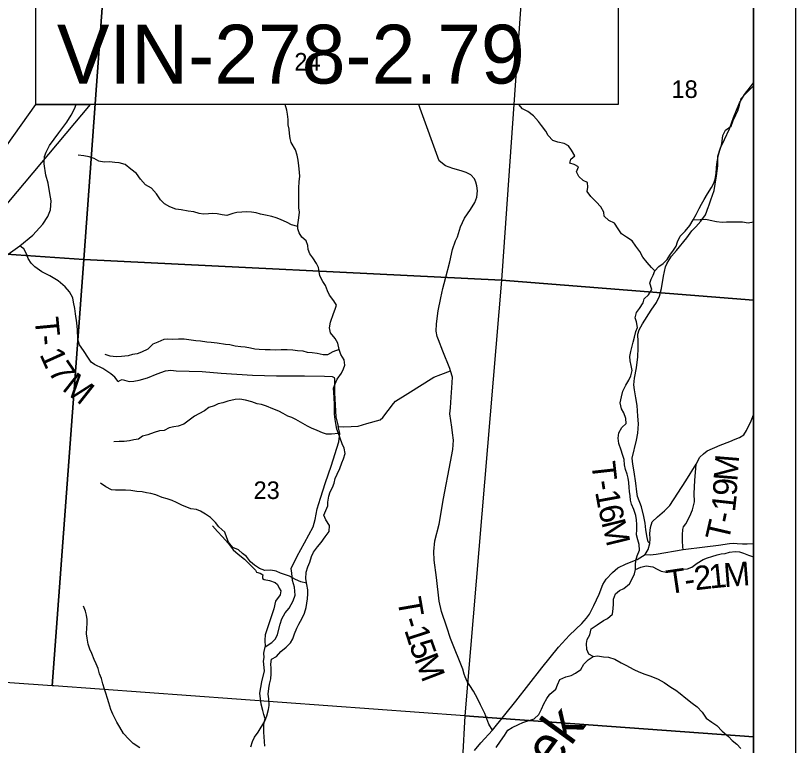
# Model space of a CAD drawing. Extents: x 0 to 34, y 0 to 22.
# Drawn here: x 7.144 to 9, y 16.66 to 18.398 of the extents above; entities that cross this region are included whole.
import ezdxf

# ---------------------------------------------------------------- set-up
doc = ezdxf.new("R2010")
doc.units = 0
for name, color, linetype in [('Default', 7, 'Continuous'), ('GM_X_County_Road', 7, 'Continuous'), ('GM_X_Minor_River', 7, 'Continuous'), ('GM_X_Minor_River_Text', 7, 'Continuous'), ('GM_X_Section', 7, 'Continuous'), ('GM_X_Section_Text', 7, 'Continuous'), ('GM_X_Township_Road', 7, 'Continuous'), ('GM_X_Township_Road_Text', 7, 'Continuous'), ('SC_Scratch1', 7, 'Continuous'), ('SH_Data', 7, 'Continuous'), ('SH_Text', 7, 'Continuous')]:
    doc.layers.add(name, color=color, linetype=linetype)

msp = doc.modelspace()

# ---------------------------------------------------------------- linework, layer by layer
at = {"layer": 'Default'}
for points in [[(8.9, 17.7203), (8.9, 18.739), (8.3709, 18.7757), (8.3007, 17.7677)], [(8.9, 16.6804), (8.9, 17.7203), (8.3007, 17.7677), (8.213, 16.7303)], [(8.9, 15.6488), (8.9, 16.6804), (8.213, 16.7303), (8.1912, 16.3241), (8.1695, 15.9195), (8.158, 15.705), (8.5934, 15.672)]]:
    msp.add_lwpolyline(points, close=True, dxfattribs=at)
at = {"layer": 'GM_X_County_Road'}
msp.add_lwpolyline([(8.2361, 16.6479), (8.2514, 16.6664), (8.2787, 16.6962), (8.3347, 16.7653), (8.396, 16.8445), (8.4361, 16.8936), (8.4623, 16.9227), (8.4917, 16.9506), (8.5026, 16.9628), (8.5098, 16.9725), (8.5203, 16.9928), (8.5325, 17.02), (8.5415, 17.0431), (8.5496, 17.0555), (8.5644, 17.072), (8.5773, 17.0825), (8.5971, 17.0927), (8.6231, 17.1023), (8.6426, 17.1142), (8.6498, 17.1266), (8.6531, 17.1404), (8.6541, 17.1519), (8.6537, 17.1648), (8.6548, 17.1791), (8.6591, 17.1924), (8.672, 17.2044), (8.6882, 17.2184), (8.7008, 17.2313), (8.7388, 17.2898), (8.7638, 17.3294), (8.7726, 17.346), (8.781, 17.3539), (8.79, 17.3611), (8.821, 17.3751), (8.8437, 17.384), (8.8563, 17.3892), (8.8668, 17.3933), (8.8771, 17.3997), (8.8835, 17.4097), (8.8943, 17.4326), (8.9, 17.4468)], dxfattribs=at)
at = {"layer": 'GM_X_Minor_River'}
for points in [[(8.8089, 18.0085), (8.8112, 18.0218), (8.8119, 18.0358), (8.8134, 18.0498), (8.8168, 18.0662), (8.8198, 18.0775), (8.824, 18.0893), (8.8259, 18.0992), (8.8274, 18.1121), (8.8338, 18.125), (8.8467, 18.1345), (8.8516, 18.1477), (8.8584, 18.1614), (8.8633, 18.1709), (8.8667, 18.1845), (8.8708, 18.2008), (8.8822, 18.2126), (8.8912, 18.2221), (8.9, 18.2307)], [(7.9044, 17.2957), (7.9093, 17.3056), (7.9153, 17.3192), (7.9199, 17.3325), (7.924, 17.342), (7.9285, 17.3553), (7.9259, 17.3674), (7.9209, 17.3784), (7.916, 17.3917), (7.9122, 17.4023), (7.9084, 17.4133), (7.9061, 17.4262), (7.9046, 17.436), (7.9027, 17.4489), (7.9027, 17.4626), (7.903, 17.4728), (7.9019, 17.4873), (7.9015, 17.5005), (7.9007, 17.5104), (7.9045, 17.521), (7.9094, 17.532), (7.9196, 17.5461), (7.9241, 17.5563), (7.9275, 17.5658), (7.9256, 17.5783), (7.9181, 17.5908), (7.9139, 17.603), (7.9108, 17.6174), (7.9048, 17.6291), (7.893, 17.6424), (7.8911, 17.6542), (7.8934, 17.6678), (7.9001, 17.6883), (7.9043, 17.6985), (7.9077, 17.7084), (7.9012, 17.7186), (7.891, 17.7323), (7.8864, 17.7422), (7.8811, 17.7551), (7.8751, 17.7649), (7.8679, 17.7778), (7.8663, 17.7881), (7.8644, 17.7979), (7.8602, 17.8078), (7.8511, 17.8207), (7.8439, 17.8305), (7.8405, 17.8411), (7.8394, 17.8506), (7.8356, 17.8612), (7.825, 17.8703), (7.8185, 17.8806), (7.8159, 17.8901), (7.8155, 17.8999), (7.8181, 17.9159), (7.8192, 17.9295), (7.8181, 17.9401), (7.8177, 17.9534), (7.8176, 17.9872), (7.8191, 18.0027), (7.8206, 18.0149), (7.8199, 18.0247), (7.8176, 18.0399), (7.8164, 18.0539), (7.8141, 18.0653), (7.8096, 18.0782), (7.7993, 18.0953), (7.7974, 18.1055), (7.7959, 18.1173), (7.7951, 18.1275), (7.7928, 18.1378), (7.7925, 18.1503), (7.7913, 18.1628), (7.789, 18.1723), (7.7855, 18.186)], [(8.6657, 17.7899), (8.6573, 17.7983), (8.6471, 17.81), (8.6369, 17.8229), (8.63, 17.8362), (8.6205, 17.8487), (8.6118, 17.8616), (8.5982, 17.8699), (8.5857, 17.8783), (8.5777, 17.8904), (8.5694, 17.9037), (8.5561, 17.9098), (8.5447, 17.9204), (8.5436, 17.9299), (8.5371, 17.9427), (8.5254, 17.9541), (8.5132, 17.967), (8.5041, 17.9792), (8.506, 17.9894), (8.5053, 18.0004), (8.495, 18.0049), (8.4848, 18.0148), (8.4791, 18.0254), (8.4836, 18.0376), (8.4734, 18.0432), (8.4632, 18.0463), (8.4651, 18.0558), (8.4749, 18.0641), (8.4673, 18.077), (8.4597, 18.0876), (8.4495, 18.0933), (8.4343, 18.0963), (8.4226, 18.1005), (8.4112, 18.1122), (8.4059, 18.1225), (8.3953, 18.1358), (8.3881, 18.1456), (8.3763, 18.1589), (8.3634, 18.1695), (8.3502, 18.1756), (8.3418, 18.186)], [(7.8156, 17.8956), (7.8007, 17.8999), (7.7905, 17.9052), (7.7746, 17.912), (7.7639, 17.9162), (7.7533, 17.9192), (7.7389, 17.9227), (7.7268, 17.9253), (7.7162, 17.928), (7.7049, 17.9298), (7.6927, 17.9302), (7.6825, 17.9298), (7.6704, 17.9287), (7.6606, 17.9268), (7.6466, 17.9219), (7.6352, 17.9234), (7.6235, 17.926), (7.6132, 17.9268), (7.603, 17.9256), (7.5913, 17.9249), (7.581, 17.9268), (7.5678, 17.9305), (7.5545, 17.932), (7.5379, 17.9351), (7.5254, 17.9366), (7.511, 17.9427), (7.4985, 17.9499), (7.489, 17.9593), (7.4791, 17.9734), (7.467, 17.987), (7.453, 17.9946), (7.4412, 18.0082), (7.4317, 18.0215), (7.4177, 18.0321), (7.4048, 18.0431), (7.3901, 18.0469), (7.3802, 18.0477), (7.367, 18.0496), (7.3545, 18.0492), (7.3416, 18.0514), (7.331, 18.0575), (7.3185, 18.0617), (7.3064, 18.0639), (7.2927, 18.0655)], [(8.5187, 16.8715), (8.5081, 16.8776), (8.5035, 16.8886), (8.5031, 16.9026), (8.5046, 16.9125), (8.5107, 16.9235), (8.514, 16.9375), (8.5284, 16.947), (8.5432, 16.9576), (8.553, 16.9622), (8.5648, 16.9724), (8.5659, 16.9861), (8.5666, 16.9963), (8.567, 17.0085), (8.5715, 17.021), (8.5813, 17.0286), (8.5916, 17.0335), (8.6048, 17.0445), (8.6124, 17.0582), (8.6173, 17.0684), (8.6192, 17.0787), (8.6191, 17.0897), (8.6199, 17.1003), (8.6237, 17.1117), (8.6289, 17.1246), (8.6278, 17.1382), (8.6251, 17.1496), (8.6221, 17.1617), (8.6225, 17.1743), (8.6228, 17.186), (8.622, 17.1974), (8.6198, 17.2076), (8.6152, 17.2217), (8.6099, 17.2342), (8.6072, 17.2437), (8.6065, 17.2543), (8.6053, 17.2642), (8.6045, 17.274), (8.6034, 17.2862), (8.6022, 17.296), (8.5992, 17.3055), (8.5958, 17.3173), (8.5931, 17.3279), (8.592, 17.3408), (8.5885, 17.3525), (8.5851, 17.3628), (8.5798, 17.3787), (8.5783, 17.3916), (8.5794, 17.4041), (8.587, 17.417), (8.5968, 17.4261), (8.5964, 17.4383), (8.5915, 17.4519), (8.5858, 17.4618), (8.5831, 17.4758), (8.5857, 17.4902), (8.5895, 17.5031), (8.5967, 17.5179), (8.6031, 17.5297), (8.6084, 17.5403), (8.6114, 17.5528), (8.6088, 17.565), (8.6065, 17.5756), (8.6061, 17.5858), (8.6083, 17.598), (8.6114, 17.6105), (8.614, 17.62), (8.6166, 17.6321), (8.6204, 17.6454), (8.6238, 17.6549), (8.6219, 17.6685), (8.6188, 17.6784), (8.6215, 17.6909), (8.6287, 17.7004), (8.6374, 17.7137), (8.64, 17.7232), (8.6506, 17.733), (8.6585, 17.7459), (8.6536, 17.7603), (8.6566, 17.7702), (8.6615, 17.7801), (8.6657, 17.7899), (8.6747, 17.8002), (8.685, 17.8074), (8.6948, 17.8169), (8.7012, 17.8271), (8.7099, 17.8389), (8.716, 17.8491), (8.7194, 17.8594), (8.7258, 17.8723), (8.7375, 17.8848), (8.7485, 17.8981), (8.7568, 17.9114), (8.7636, 17.9243), (8.7708, 17.9383), (8.7764, 17.9486), (8.7832, 17.9596), (8.7904, 17.9736), (8.7999, 17.9884), (8.8055, 17.999), (8.8089, 18.0085)], [(8.7568, 17.9114), (8.7734, 17.9121), (8.7871, 17.9133), (8.7973, 17.9106), (8.8121, 17.9072), (8.8253, 17.9061), (8.8363, 17.9065), (8.8738, 17.9065), (8.8878, 17.9046), (8.9, 17.9066)], [(7.9139, 17.603), (7.8991, 17.5969), (7.8862, 17.5897), (7.876, 17.5897), (7.8613, 17.5934), (7.8499, 17.595), (7.8385, 17.5953), (7.8283, 17.5984), (7.8147, 17.5999), (7.8037, 17.601), (7.7901, 17.6018), (7.7757, 17.6018), (7.7632, 17.601), (7.7495, 17.6017), (7.7378, 17.6021), (7.7238, 17.6029), (7.7132, 17.6036), (7.7026, 17.6059), (7.6901, 17.6082), (7.6802, 17.6089), (7.6662, 17.6108), (7.6537, 17.6138), (7.6431, 17.615), (7.6238, 17.6176), (7.609, 17.6191), (7.5992, 17.6203), (7.584, 17.6222), (7.5727, 17.6233), (7.5564, 17.6256), (7.5447, 17.6274), (7.5314, 17.6271), (7.5178, 17.6267), (7.5064, 17.6274), (7.4966, 17.6267), (7.4826, 17.6202), (7.4705, 17.6153), (7.4583, 17.6039), (7.4432, 17.5963), (7.433, 17.5925), (7.4216, 17.591), (7.4114, 17.5879), (7.3955, 17.5864), (7.383, 17.5856), (7.369, 17.5868), (7.3569, 17.5906)], [(7.912, 17.4029), (7.8959, 17.4011), (7.8838, 17.4008), (7.8743, 17.4042), (7.8618, 17.4099), (7.8482, 17.4155), (7.8384, 17.4205), (7.8277, 17.4265), (7.8111, 17.436), (7.8016, 17.4406), (7.7921, 17.4443), (7.7808, 17.4504), (7.7705, 17.4557), (7.7561, 17.4618), (7.741, 17.4675), (7.7289, 17.4716), (7.719, 17.4731), (7.7061, 17.4777), (7.691, 17.4818), (7.6777, 17.4841), (7.666, 17.4837), (7.6493, 17.4796), (7.6372, 17.4761), (7.6262, 17.4731), (7.6164, 17.4685), (7.6039, 17.4644), (7.5933, 17.4564), (7.5801, 17.4499), (7.5695, 17.4442), (7.557, 17.4344), (7.5438, 17.4253), (7.5305, 17.4199), (7.5207, 17.4188), (7.5089, 17.4158), (7.4976, 17.4101), (7.4866, 17.4089), (7.4737, 17.4047), (7.4586, 17.3998), (7.4457, 17.396), (7.4359, 17.3895), (7.4253, 17.3876), (7.4147, 17.3854), (7.4022, 17.3838), (7.3904, 17.3835), (7.3776, 17.3831)], [(7.8364, 17.0462), (7.8225, 17.0495), (7.8096, 17.0548), (7.7956, 17.0627), (7.7861, 17.0665), (7.774, 17.0699), (7.7642, 17.0745), (7.7509, 17.0771), (7.7373, 17.0767), (7.7244, 17.0813), (7.7126, 17.0889), (7.7032, 17.0972), (7.6937, 17.1101), (7.6842, 17.1173), (7.6744, 17.1253), (7.6611, 17.1309), (7.6501, 17.1442), (7.6467, 17.1545), (7.6414, 17.1674), (7.6273, 17.1806), (7.6198, 17.1905), (7.608, 17.2026), (7.5959, 17.2102), (7.5841, 17.2178), (7.5747, 17.2216), (7.561, 17.2231), (7.5512, 17.2276), (7.5413, 17.231), (7.5265, 17.2382), (7.5167, 17.2435), (7.5042, 17.2473), (7.4925, 17.2504), (7.4777, 17.2568), (7.4659, 17.2595), (7.455, 17.2617), (7.4447, 17.2636), (7.4319, 17.2647), (7.4178, 17.2666), (7.4057, 17.2674), (7.3951, 17.2674), (7.3815, 17.2681), (7.3716, 17.2685), (7.3584, 17.2753), (7.3455, 17.2841)], [(7.7033, 16.6568), (7.7074, 16.6689), (7.7127, 16.6792), (7.721, 16.6917), (7.7369, 16.7175), (7.7418, 16.7304), (7.7456, 16.7456), (7.7475, 16.7551), (7.7463, 16.771), (7.7452, 16.7816), (7.7467, 16.7957), (7.7478, 16.8055), (7.7512, 16.8184), (7.7523, 16.8306), (7.7523, 16.8442), (7.7515, 16.8537), (7.7527, 16.8651), (7.7651, 16.8719), (7.775, 16.8833), (7.7875, 16.8935), (7.798, 16.9042), (7.8037, 16.9137), (7.8079, 16.9254), (7.8132, 16.9391), (7.8177, 16.9486), (7.826, 16.9626), (7.8317, 16.9747), (7.8351, 16.988), (7.8373, 16.9983), (7.8384, 17.0093), (7.8392, 17.021), (7.8392, 17.0305), (7.8369, 17.0434), (7.8346, 17.0567), (7.8353, 17.0722), (7.8391, 17.0851), (7.844, 17.0961), (7.8482, 17.1094), (7.8531, 17.12), (7.8622, 17.1326), (7.8709, 17.1428), (7.8807, 17.1565), (7.8898, 17.1697), (7.8909, 17.1834), (7.8825, 17.1971), (7.8776, 17.2081), (7.8825, 17.2194), (7.887, 17.2301), (7.887, 17.2395), (7.8893, 17.2536), (7.8927, 17.2638), (7.8983, 17.2737), (7.9017, 17.2843), (7.9044, 17.2957)], [(8.6192, 17.0787), (8.632, 17.0847), (8.6449, 17.0878), (8.6604, 17.0848), (8.6707, 17.0795), (8.6801, 17.0749), (8.6934, 17.0726), (8.7063, 17.0761), (8.7176, 17.0787), (8.7324, 17.0795), (8.7434, 17.0806), (8.7532, 17.0844), (8.7664, 17.0939), (8.7801, 17.103), (8.791, 17.1064), (8.8013, 17.1099), (8.8134, 17.114), (8.8232, 17.1163), (8.8331, 17.1171), (8.8433, 17.1201), (8.8565, 17.122), (8.8667, 17.1209), (8.8762, 17.1175), (8.8887, 17.1129), (8.8982, 17.1099), (8.9, 17.1099)], [(7.4394, 16.6544), (7.4235, 16.6643), (7.4136, 16.6752), (7.4007, 16.6885), (7.3916, 16.7033), (7.3848, 16.7154), (7.3798, 16.7249), (7.3749, 16.7344), (7.3703, 16.7454), (7.3658, 16.7617), (7.3627, 16.772), (7.3582, 16.7841), (7.3555, 16.7936), (7.3517, 16.8065), (7.3483, 16.8194), (7.3434, 16.8307), (7.3399, 16.8429), (7.3354, 16.8543), (7.3308, 16.8645), (7.3248, 16.8789), (7.3202, 16.8895), (7.3168, 16.9013), (7.3141, 16.9157), (7.3122, 16.9256), (7.3133, 16.9396), (7.3137, 16.9495), (7.3137, 16.9601), (7.3122, 16.9699), (7.3103, 16.9798), (7.3053, 16.9919)], [(8.2876, 16.6548), (8.2978, 16.67), (8.3072, 16.6836), (8.3155, 16.6965), (8.3261, 16.7026), (8.3409, 16.7098), (8.3515, 16.7144), (8.378, 16.7235), (8.3893, 16.7337), (8.3958, 16.7459), (8.401, 16.7592), (8.4086, 16.7717), (8.4154, 16.7816), (8.4294, 16.7937), (8.4339, 16.8039), (8.4396, 16.8165), (8.4532, 16.8229), (8.4665, 16.8267), (8.4763, 16.8317), (8.4892, 16.8408), (8.4964, 16.8533), (8.5066, 16.8639), (8.5187, 16.8715), (8.5289, 16.873), (8.5429, 16.8711), (8.555, 16.87), (8.5698, 16.8651), (8.585, 16.8567), (8.5963, 16.8514), (8.6153, 16.8408), (8.627, 16.8351), (8.6418, 16.8295), (8.6531, 16.8257), (8.6634, 16.8219), (8.6732, 16.8173), (8.6872, 16.8098), (8.7035, 16.7988), (8.7157, 16.7912), (8.7259, 16.7836), (8.7395, 16.7722), (8.7543, 16.7605), (8.7664, 16.7521), (8.7778, 16.7392), (8.7873, 16.7252), (8.8009, 16.7153), (8.8127, 16.707), (8.826, 16.6937), (8.8407, 16.6808), (8.8498, 16.6714), (8.8608, 16.6627), (8.8703, 16.6528)]]:
    msp.add_lwpolyline(points, dxfattribs=at)
at = {"layer": 'GM_X_Section'}
for points in [[(6.4104, 18.9115), (7.3808, 18.8429), (7.3065, 17.8168), (6.3391, 17.8836)], [(8.3709, 18.7757), (8.3007, 17.7677), (7.3065, 17.8168), (7.3808, 18.8429)], [(6.3391, 17.8836), (7.3065, 17.8168), (7.2305, 16.8022), (6.2455, 16.872)], [(7.3065, 17.8168), (8.3007, 17.7677), (8.213, 16.7303), (7.2351, 16.8019), (7.2305, 16.8022)]]:
    msp.add_lwpolyline(points, close=True, dxfattribs=at)
at = {"layer": 'GM_X_Township_Road'}
for points in [[(8.793, 17.9433), (8.7936, 17.9452), (8.7989, 17.9588), (8.8067, 17.981), (8.8125, 18.0159), (8.8152, 18.0401), (8.8156, 18.0634), (8.8214, 18.0832), (8.8314, 18.1031), (8.8431, 18.1282), (8.8529, 18.155), (8.8671, 18.1899), (8.8785, 18.2102), (8.8928, 18.2283), (8.9, 18.238)], [(7.154, 17.8492), (7.1845, 17.8749), (7.2089, 17.901), (7.2205, 17.9195), (7.2264, 17.935), (7.2283, 17.9564), (7.2254, 17.9741), (7.2209, 17.9985), (7.2155, 18.0178), (7.2115, 18.0452), (7.2124, 18.0624), (7.2164, 18.0727), (7.2242, 18.0883), (7.247, 18.1185), (7.2659, 18.1443), (7.2758, 18.1607), (7.2836, 18.1761), (7.2875, 18.186)], [(8.1559, 17.7257), (8.1608, 17.7481), (8.1674, 17.772), (8.1775, 17.8111), (8.1837, 17.8405), (8.1907, 17.8614), (8.196, 17.8712), (8.203, 17.8945), (8.2123, 17.9154), (8.2265, 17.9364), (8.2372, 17.9529), (8.2415, 17.9654), (8.2436, 17.9805), (8.2419, 17.9926), (8.2394, 18.001), (8.2359, 18.0095), (8.2277, 18.0183), (8.2164, 18.0241), (8.204, 18.0284), (8.1843, 18.0335), (8.1674, 18.0397), (8.152, 18.0517), (8.1065, 18.1768), (8.1033, 18.186)], [(8.6531, 17.1404), (8.6498, 17.1447), (8.6474, 17.1548), (8.6443, 17.1731), (8.6424, 17.1891), (8.6393, 17.2048), (8.6333, 17.2282), (8.6245, 17.253), (8.6224, 17.264), (8.6205, 17.2847), (8.6162, 17.3115), (8.6128, 17.3298), (8.6114, 17.3437), (8.6214, 17.3866), (8.625, 17.4035), (8.6264, 17.4255), (8.6252, 17.4443), (8.6236, 17.4696), (8.6202, 17.4875), (8.6167, 17.5063), (8.6157, 17.5183), (8.6169, 17.5347), (8.6219, 17.559), (8.6248, 17.5855), (8.626, 17.606), (8.6257, 17.6206), (8.6252, 17.6392), (8.6284, 17.6497), (8.6364, 17.664), (8.6565, 17.6967), (8.6694, 17.715), (8.6768, 17.7296), (8.6813, 17.7482), (8.6863, 17.7773), (8.6908, 17.7992), (8.6939, 17.8065), (8.6996, 17.8162), (8.7049, 17.8252), (8.7172, 17.8387), (8.7412, 17.8687), (8.7535, 17.8853), (8.7626, 17.8947), (8.775, 17.9082), (8.7862, 17.9235), (8.793, 17.9433)], [(7.1205, 17.8261), (7.154, 17.8492)], [(7.3882, 17.5263), (7.3799, 17.5366), (7.3701, 17.5451), (7.3515, 17.5572), (7.3312, 17.5673), (7.3236, 17.5726), (7.317, 17.5817), (7.3057, 17.6002), (7.2962, 17.614), (7.2915, 17.6276), (7.2912, 17.6492), (7.2894, 17.666), (7.2863, 17.6877), (7.2845, 17.7), (7.2818, 17.7158), (7.2797, 17.7259), (7.2721, 17.7401), (7.2614, 17.7523), (7.2454, 17.7663), (7.225, 17.778), (7.2059, 17.7879), (7.1896, 17.7996), (7.181, 17.8084), (7.1738, 17.8198), (7.1707, 17.8286), (7.1635, 17.8426), (7.1581, 17.8461), (7.154, 17.8492)], [(8.2117, 16.8299), (8.208, 16.8413), (8.2006, 16.8615), (8.1886, 16.8905), (8.1787, 16.9146), (8.1703, 16.9417), (8.1578, 16.9792), (8.1518, 17.0033), (8.1458, 17.0601), (8.1403, 17.1012), (8.1392, 17.122), (8.1415, 17.1473), (8.1518, 17.1864), (8.1621, 17.2481), (8.1787, 17.3354), (8.1845, 17.3644), (8.1865, 17.3868), (8.1841, 17.4041), (8.1818, 17.4181), (8.1777, 17.4496), (8.1787, 17.4638), (8.1804, 17.4891), (8.1824, 17.5117), (8.1835, 17.5366), (8.179, 17.5518), (8.1773, 17.5576), (8.1606, 17.5986), (8.1501, 17.6257), (8.1475, 17.634), (8.1448, 17.6464), (8.1455, 17.6642), (8.1493, 17.6949), (8.1559, 17.7257)], [(7.3882, 17.5263), (7.3933, 17.53), (7.3971, 17.5311), (7.4029, 17.5295), (7.4143, 17.5269), (7.4254, 17.5275), (7.4381, 17.5293), (7.4577, 17.5355), (7.4808, 17.5444), (7.5007, 17.5523), (7.5135, 17.5534), (7.526, 17.5521), (7.5882, 17.5501), (7.6333, 17.5466), (7.708, 17.5416), (7.7646, 17.5404), (7.8314, 17.5397)], [(7.8314, 17.5397), (7.8791, 17.5391), (7.8971, 17.5384), (7.9017, 17.5364), (7.903, 17.5318), (7.9028, 17.5193), (7.9026, 17.4986), (7.9061, 17.4425), (7.9114, 17.4195), (7.9252, 17.4189), (7.9422, 17.4191), (7.9593, 17.4199), (7.9799, 17.4266), (8.0117, 17.4354), (8.0175, 17.4405), (8.043, 17.4744), (8.048, 17.4799), (8.077, 17.4977), (8.1393, 17.5369), (8.1557, 17.5428), (8.179, 17.5518)], [(7.7373, 16.6585), (7.735, 16.6918), (7.7343, 16.7117), (7.7379, 16.7236), (7.7344, 16.7338), (7.7319, 16.7433), (7.7285, 16.7579), (7.7248, 16.7841), (7.7298, 16.8115), (7.7363, 16.8378), (7.7342, 16.8607), (7.7355, 16.869), (7.735, 16.8792), (7.7377, 16.8944), (7.7536, 16.9053), (7.7625, 16.9134), (7.7674, 16.924), (7.7731, 16.9487), (7.7775, 16.9617), (7.7852, 16.9755), (7.795, 16.9864), (7.8043, 17.0042), (7.8091, 17.0176), (7.8075, 17.0367), (7.8031, 17.0529), (7.801, 17.0703), (7.7997, 17.0813), (7.8136, 17.1105), (7.8314, 17.1425), (7.8517, 17.1802), (7.857, 17.1977), (7.8619, 17.2232), (7.8692, 17.2483), (7.8813, 17.2861), (7.8951, 17.3246), (7.9134, 17.3826), (7.9158, 17.4028), (7.9114, 17.4195)], [(8.7328, 17.1261), (8.7321, 17.1331), (8.7314, 17.1474), (8.7309, 17.1617), (8.7319, 17.1738), (8.7337, 17.1805), (8.7388, 17.1879), (8.7483, 17.2056), (8.755, 17.2206), (8.7595, 17.2397), (8.7593, 17.2597), (8.7602, 17.2909), (8.7638, 17.3294)], [(7.6121, 17.1827), (7.6247, 17.1697), (7.636, 17.1567), (7.6494, 17.1413), (7.662, 17.1259), (7.6733, 17.1153), (7.6883, 17.1032), (7.7001, 17.0918), (7.7052, 17.0864), (7.7116, 17.0807), (7.7145, 17.077), (7.7171, 17.0724), (7.7256, 17.0703), (7.7301, 17.0679), (7.7321, 17.0659), (7.7317, 17.0624), (7.7317, 17.0574), (7.7351, 17.0553), (7.7479, 17.0525), (7.7619, 17.0476), (7.767, 17.0434), (7.771, 17.0347), (7.7751, 17.028), (7.7738, 17.0184), (7.7621, 17.0038), (7.7585, 16.9852), (7.752, 16.9661), (7.7431, 16.9398), (7.7378, 16.9235), (7.737, 16.9102), (7.7377, 16.8944)], [(8.6426, 17.1142), (8.6546, 17.1135), (8.6686, 17.1156), (8.7328, 17.1261), (8.7844, 17.1328), (8.8171, 17.1369), (8.8432, 17.1404), (8.8525, 17.1417), (8.8611, 17.1406), (8.8742, 17.14), (8.8853, 17.14), (8.9, 17.1404)], [(8.2787, 16.6962), (8.2705, 16.7105), (8.2608, 16.7362), (8.2505, 16.7563), (8.2434, 16.772), (8.2337, 16.7893), (8.2252, 16.8024), (8.2186, 16.8125), (8.2139, 16.8232), (8.2117, 16.8299)]]:
    msp.add_lwpolyline(points, dxfattribs=at)
at = {"layer": 'SC_Scratch1'}
msp.add_lwpolyline([(5.0535, 14.1), (8.9, 14.1), (8.9, 18.7389), (8.2061, 18.7863), (7.2159, 18.8539), (6.8273, 18.8804), (5.9889, 18.9377), (5.4885, 18.9719), (5.4007, 18.9779), (5.3662, 18.4999), (5.3506, 18.2846), (5.2869, 17.4026), (5.2761, 17.2534), (5.1794, 15.9156), (5.1049, 14.8414), (5.0814, 14.5016)], close=True, dxfattribs=at)
at = {"layer": 'SH_Data'}
for p, q in [((9, 21), (9, 14)), ((8.9, 20.9), (8.9, 14.1))]:
    msp.add_line(p, q, dxfattribs=at)
at = {"layer": 'SH_Text'}
for points in [[(8.5782, 18.186), (7.1921, 18.186), (7.1921, 18.426), (8.5782, 18.426)], [(6.4807, 17.185), (7.1921, 18.186), (7.3213, 18.186), (6.4807, 17.185)]]:
    msp.add_lwpolyline(points, close=True, dxfattribs=at)

# ---------------------------------------------------------------- texts
at = {"layer": 'GM_X_Minor_River_Text'}
msp.add_text('Creek', height=0.0947, rotation=53.9563, dxfattribs=at).set_placement((8.3038, 16.4346))
at = {"layer": 'GM_X_Section_Text'}
for s, p in [('24', (7.8073, 18.267)), ('18', (8.7052, 18.2017)), ('23', (7.7102, 17.2467))]:
    msp.add_text(s, height=0.04186, rotation=0, dxfattribs=at).set_placement(p)
at = {"layer": 'GM_X_Township_Road_Text'}
for s, rotation, p in [('T', 275.4164, (7.1888, 17.6776)), ('-', 274.0784, (7.1928, 17.6357)), ('1', 294.264, (7.1998, 17.5913)), ('7', 304.0326, (7.2193, 17.5502)), ('M', 321.6464, (7.2518, 17.5073)), ('M', 85.3273, (8.8615, 17.2874)), ('T', 276.3558, (8.5142, 17.3333)), ('-', 278.7648, (8.5192, 17.2884)), ('9', 87.6977, (8.8602, 17.2534)), ('1', 280.3571, (8.523, 17.2637)), ('1', 83.6062, (8.856, 17.2144)), ('6', 282.7193, (8.5299, 17.2268)), ('-', 78.2839, (8.8504, 17.1861)), ('M', 283.7057, (8.5378, 17.1916)), ('T', 76.902, (8.8404, 17.1433)), ('M', 4.4021, (8.8308, 17.0367)), ('T', 8.335, (8.6971, 17.0199)), ('2', 6.7597, (8.7618, 17.0292)), ('1', 5.723, (8.7963, 17.0333)), ('-', 7.8453, (8.739, 17.026)), ('T', 279.7759, (8.0522, 17.0078)), ('-', 286.8354, (8.0612, 16.9585)), ('1', 288.0131, (8.0684, 16.935)), ('5', 289.689, (8.0798, 16.9)), ('M', 290.9175, (8.092, 16.8658))]:
    msp.add_text(s, height=0.0568, rotation=rotation, dxfattribs=at).set_placement(p)
at = {"layer": 'SH_Text'}
msp.add_text('VIN-278-2.79', height=0.14, dxfattribs=at).set_placement((7.2421, 18.236))

doc.saveas('drawing.dxf')
